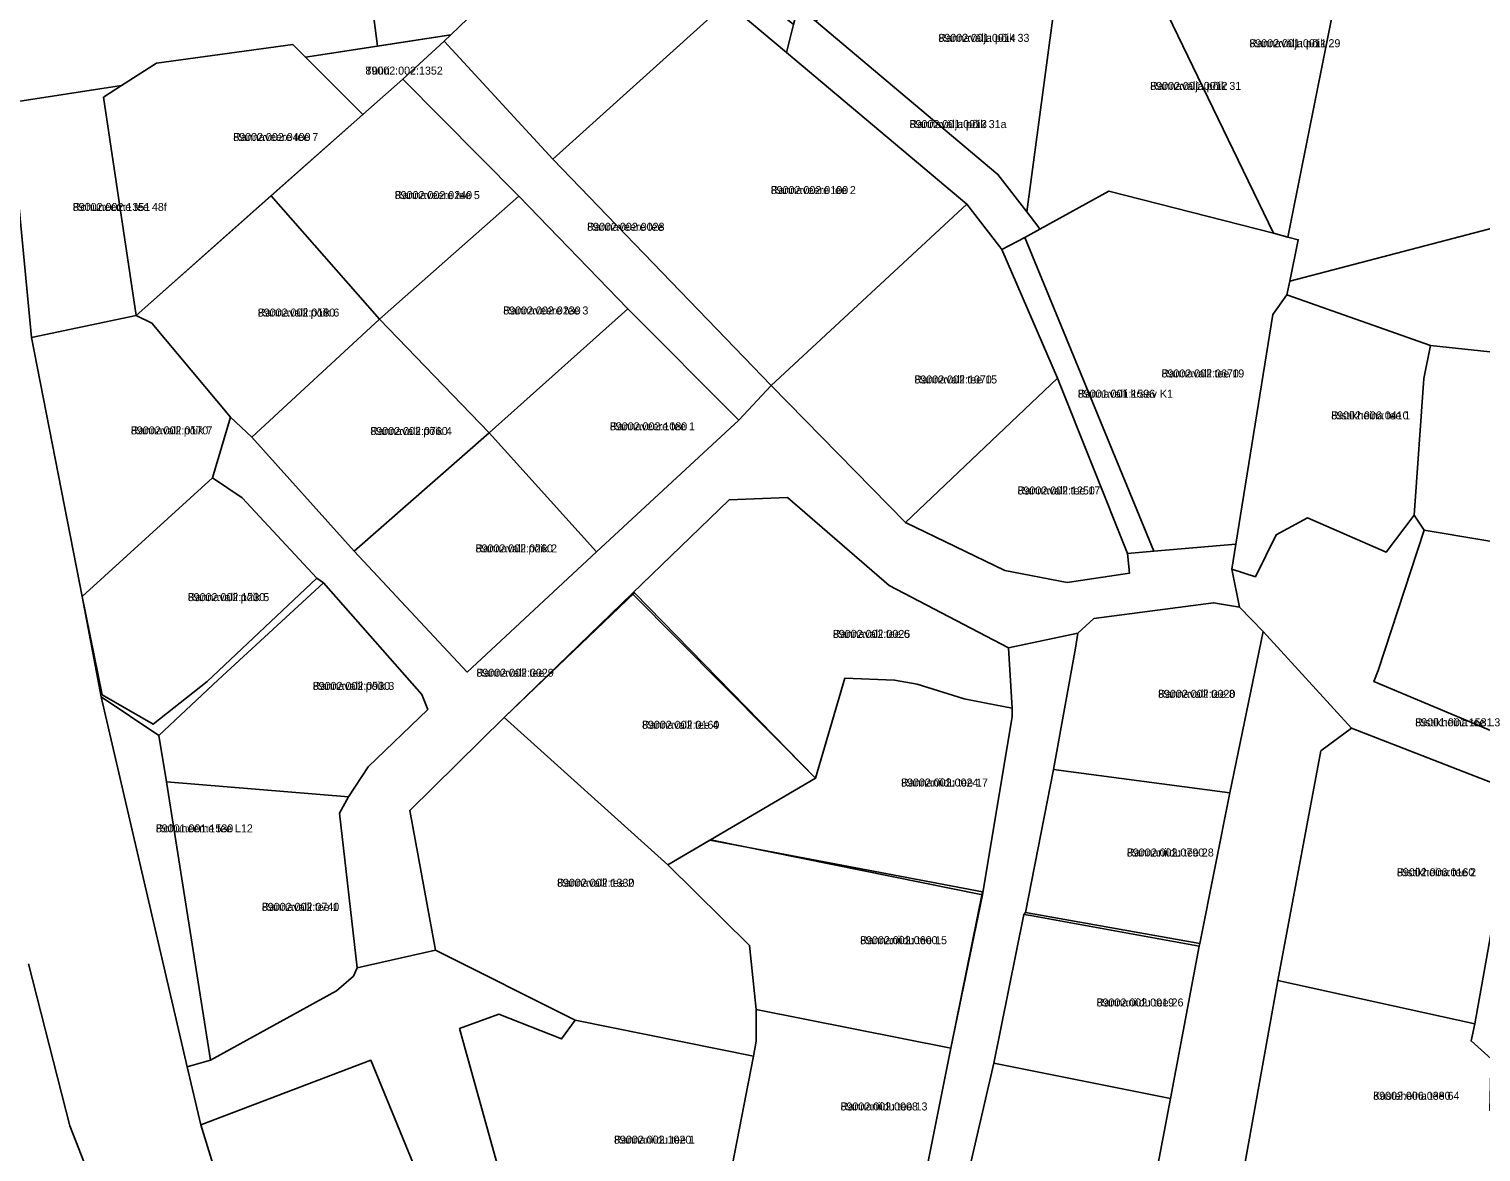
# Model space of a CAD drawing. Extents: x 526849 to 562296, y 6591741 to 6618546.
# Drawn here: x 545079.1 to 545351.2, y 6599278.2 to 6599488.6 of the extents above; entities that cross this region are included whole.
import ezdxf

# ---------------------------------------------------------------- set-up
doc = ezdxf.new("R2010")
doc.units = 0
for name, color, linetype in [('L_AADRESS', 7, 'Continuous'), ('PIIR', 7, 'Continuous'), ('TUNNUS', 7, 'Continuous')]:
    doc.layers.add(name, color=color, linetype=linetype)

msp = doc.modelspace()

# ---------------------------------------------------------------- linework, layer by layer
at = {"layer": 'PIIR'}
for points in [[(545405.74, 6599650.28), (545389.3, 6599566.67), (545376.43, 6599503.88), (545367.66, 6599457.32), (545373.86, 6599456.64), (545315.4, 6599441.37), (545316.99, 6599449.14), (545315.05, 6599449.64), (545318.74, 6599468.03), (545327.84, 6599513.78), (545329.66, 6599522.77), (545334.02, 6599544.69), (545338.46, 6599566.76), (545341.92, 6599584.34), (545343.79, 6599593.87), (545346.85, 6599609.12), (545353.41, 6599641.84), (545356.94, 6599659.68)], [(545219.07, 6599657.56), (545210.56, 6599616.75), (545209.57, 6599612.32), (545202.52, 6599580.46), (545198.72, 6599563.34), (545191.91, 6599531.05), (545190.99, 6599524.12), (545191.51, 6599518.55), (545193.48, 6599514.29), (545197.05, 6599510.92), (545213.13, 6599497.04), (545222.37, 6599489.43), (545221.07, 6599484.2), (545209.87, 6599493.59), (545188.88, 6599516.39), (545185.2, 6599519.83), (545185.44, 6599525.77), (545192.45, 6599555.16), (545199.86, 6599586.6), (545206.47, 6599614.63), (545212.72, 6599645.15)], [(545161.38, 6599490.6), (545158.2, 6599487.55), (545144.45, 6599485.43), (545139.36, 6599524.52)], [(545075.42, 6599474.76), (545079.57, 6599430.82), (545089.09, 6599382.3), (545092.64, 6599363.49), (545108.78, 6599294.19), (545111.31, 6599283.27), (545121.94, 6599248.78)], [(545287.34, 6599258.34), (545293.06, 6599288.24), (545298.44, 6599316.78), (545298.54, 6599317.27), (545304.14, 6599345.48), (545310.42, 6599375.7), (545326.93, 6599357.61), (545321.18, 6599353.36), (545313.14, 6599310.34), (545306.14, 6599271.41)], [(545245.73, 6599267.08), (545251.84, 6599297.64), (545257.81, 6599326.38), (545263.37, 6599359.83), (545263.37, 6599361.37), (545262.7, 6599372.66), (545275.68, 6599375.4), (545275.22, 6599372.58), (545271.14, 6599349.86), (545265.89, 6599323.09), (545265.55, 6599322.7), (545259.91, 6599294.83), (545253.11, 6599265.42)], [(545156.14, 6599263.74), (545143.19, 6599295.41), (545111.31, 6599283.27), (545108.78, 6599294.19), (545113.11, 6599295.38), (545136.77, 6599308.43), (545139.9, 6599311.17), (545140.61, 6599312.71), (545155.32, 6599315.99), (545181.44, 6599302.92), (545178.92, 6599299.39), (545167.16, 6599304.04), (545159.81, 6599301.33), (545170.81, 6599261.82)], [(545093.24, 6599266.51), (545086.79, 6599283.13), (545079, 6599313.45)], [(545079, 6599313.45), (545086.79, 6599283.13), (545093.24, 6599266.51)]]:
    msp.add_lwpolyline(points, dxfattribs=at)
for points in [[(545139.36, 6599524.52), (545144.45, 6599485.43), (545130.94, 6599483.34), (545128.54, 6599485.74), (545103.01, 6599482.21), (545096.48, 6599478.02), (545075.42, 6599474.76), (545071.2, 6599518.36)], [(545209.87, 6599493.59), (545177.29, 6599464.21), (545156.9, 6599486.32), (545158.2, 6599487.55), (545161.38, 6599490.6), (545188.88, 6599516.39)], [(545294.41, 6599508.59), (545327.84, 6599513.78), (545318.74, 6599468.03), (545315.05, 6599449.64), (545312.35, 6599450.34), (545287.77, 6599501.13), (545291.51, 6599504.25)], [(545228.74, 6599498.45), (545268.16, 6599504.54), (545272.37, 6599501), (545266.11, 6599454.34), (545260.71, 6599461.36), (545226.69, 6599489.93)], [(545272.37, 6599501), (545277.72, 6599499.07), (545283.35, 6599499.29), (545287.77, 6599501.13), (545312.35, 6599450.34), (545281.51, 6599458.26), (545268.57, 6599451.12), (545268.15, 6599451.67), (545266.11, 6599454.34)], [(545254.9, 6599455.8), (545218.23, 6599421.79), (545177.29, 6599464.21), (545209.87, 6599493.59), (545221.07, 6599484.2)], [(545223.27, 6599492.8), (545226.69, 6599489.93), (545260.71, 6599461.36), (545266.11, 6599454.34), (545268.15, 6599451.67), (545268.57, 6599451.12), (545265.71, 6599449.54), (545261.41, 6599447.3), (545261.06, 6599447.78), (545254.9, 6599455.8), (545221.07, 6599484.2), (545222.37, 6599489.43), (545222.91, 6599491.31)], [(545158.2, 6599487.55), (545156.9, 6599486.32), (545149.2, 6599479.24), (545141.7, 6599472.58), (545130.94, 6599483.34)], [(545099.22, 6599434.93), (545093.06, 6599475.82), (545096.48, 6599478.02), (545103.01, 6599482.21), (545128.54, 6599485.74), (545130.94, 6599483.34), (545141.7, 6599472.58), (545124.46, 6599457.34)], [(545218.23, 6599421.79), (545212.13, 6599415.32), (545191.37, 6599436.16), (545170.9, 6599457.29), (545149.2, 6599479.24), (545156.9, 6599486.32), (545177.29, 6599464.21)], [(545141.7, 6599472.58), (545149.2, 6599479.24), (545170.9, 6599457.29), (545144.78, 6599434.27), (545124.5, 6599457.33)], [(545096.48, 6599478.02), (545093.06, 6599475.82), (545099.22, 6599434.93), (545079.57, 6599430.82), (545075.42, 6599474.76)], [(545314.83, 6599438.78), (545315.4, 6599441.37), (545373.86, 6599456.64), (545446.15, 6599449.22), (545466.37, 6599454.08), (545508.73, 6599465.77), (545513.69, 6599449.89), (545413.33, 6599420.67), (545376.31, 6599425.64), (545341.78, 6599429.33)], [(545116.85, 6599415.88), (545102.15, 6599433.53), (545099.22, 6599434.93), (545124.5, 6599457.33), (545144.78, 6599434.27), (545120.88, 6599412.15)], [(545144.78, 6599434.27), (545170.9, 6599457.29), (545191.37, 6599436.16), (545165.36, 6599412.97)], [(545281.51, 6599458.26), (545312.35, 6599450.34), (545315.05, 6599449.64), (545316.99, 6599449.14), (545315.4, 6599441.37), (545314.83, 6599438.78), (545312.21, 6599435.13), (545305.28, 6599392.09), (545289.94, 6599390.81), (545265.71, 6599449.54), (545268.57, 6599451.12)], [(545271.86, 6599423.21), (545243.35, 6599396.13), (545218.23, 6599421.79), (545254.9, 6599455.8), (545261.06, 6599447.78), (545261.41, 6599447.3)], [(545265.71, 6599449.54), (545289.94, 6599390.81), (545285, 6599390.36), (545271.86, 6599423.21), (545261.41, 6599447.3)], [(545312.86, 6599393.85), (545308.96, 6599385.98), (545304.52, 6599387.4), (545305.28, 6599392.09), (545312.21, 6599435.13), (545314.83, 6599438.78), (545341.78, 6599429.33), (545340.51, 6599423.13), (545338.71, 6599397.5), (545333.45, 6599390.58), (545318.7, 6599397.03)], [(545165.36, 6599412.97), (545191.37, 6599436.16), (545212.13, 6599415.32), (545185.48, 6599390.68)], [(545079.57, 6599430.82), (545099.22, 6599434.93), (545102.15, 6599433.53), (545116.85, 6599415.88), (545113.48, 6599404.49), (545089.09, 6599382.3)], [(545120.88, 6599412.15), (545144.78, 6599434.27), (545165.36, 6599412.97), (545140.03, 6599390.8)], [(545338.71, 6599397.5), (545340.51, 6599423.13), (545341.78, 6599429.33), (545376.31, 6599425.64), (545375.21, 6599419.53), (545372.61, 6599389.33), (545340.58, 6599394.69)], [(545261.97, 6599387.18), (545243.35, 6599396.13), (545271.86, 6599423.21), (545285, 6599390.36), (545285.38, 6599386.68), (545273.65, 6599384.92)], [(545155.32, 6599315.99), (545140.61, 6599312.71), (545137.32, 6599341.71), (545139, 6599344.73), (545142.65, 6599350.34), (545153.83, 6599361.09), (545152.76, 6599363.95), (545134.3, 6599384.82), (545133.04, 6599385.73), (545119.04, 6599400.76), (545113.48, 6599404.49), (545116.85, 6599415.88), (545120.88, 6599412.15), (545140.03, 6599390.8), (545161.24, 6599368.13), (545185.48, 6599390.68), (545212.13, 6599415.32), (545218.23, 6599421.79), (545243.35, 6599396.13), (545261.97, 6599387.18), (545273.65, 6599384.92), (545285.38, 6599386.68), (545285, 6599390.36), (545289.94, 6599390.81), (545305.28, 6599392.09), (545304.52, 6599387.4), (545305.97, 6599380.3), (545301.12, 6599381.13), (545278.64, 6599378.16), (545275.68, 6599375.4), (545262.7, 6599372.66), (545240.34, 6599384.37), (545221.25, 6599400.84), (545210.31, 6599400.37), (545192.17, 6599382.84), (545168.18, 6599359.61), (545150.48, 6599342.22)], [(545140.03, 6599390.8), (545165.36, 6599412.97), (545185.48, 6599390.68), (545161.24, 6599368.13)], [(545092.82, 6599363.87), (545089.09, 6599382.3), (545113.48, 6599404.49), (545119.04, 6599400.76), (545133.04, 6599385.73), (545112.53, 6599366.38), (545102.37, 6599358.36)], [(545192.17, 6599382.84), (545210.31, 6599400.37), (545221.25, 6599400.84), (545240.34, 6599384.37), (545262.7, 6599372.66), (545263.37, 6599361.37), (545258.48, 6599362.31), (545254.37, 6599363.12), (545245.56, 6599365.87), (545241.34, 6599366.62), (545232.03, 6599366.98), (545226.52, 6599348.22)], [(545308.96, 6599385.98), (545312.86, 6599393.85), (545318.7, 6599397.03), (545333.45, 6599390.58), (545338.71, 6599397.5), (545340.58, 6599394.69), (545331.93, 6599368.39), (545331.17, 6599366.34), (545368.2, 6599350.83), (545403.96, 6599334.94), (545411.28, 6599331.68), (545418.49, 6599329.94), (545420.77, 6599318.43), (545383.36, 6599334.01), (545357.8, 6599345.64), (545326.93, 6599357.61), (545310.42, 6599375.7), (545305.97, 6599380.3), (545304.52, 6599387.4)], [(545331.93, 6599368.39), (545340.58, 6599394.69), (545372.61, 6599389.33), (545369.16, 6599355.14), (545368.2, 6599350.83), (545331.17, 6599366.34)], [(545134.3, 6599384.82), (545152.76, 6599363.95), (545153.83, 6599361.09), (545142.65, 6599350.34), (545139, 6599344.73), (545104.88, 6599347.56), (545103.44, 6599356.26), (545114.56, 6599366.66)], [(545226.52, 6599348.22), (545206.85, 6599336.69), (545198.84, 6599332.02), (545168.18, 6599359.61), (545192.6, 6599382.98)], [(545271.14, 6599349.86), (545275.22, 6599372.58), (545275.68, 6599375.4), (545278.64, 6599378.16), (545301.12, 6599381.13), (545305.97, 6599380.3), (545310.42, 6599375.7), (545304.14, 6599345.48)], [(545206.85, 6599336.69), (545226.52, 6599348.22), (545232.03, 6599366.98), (545241.34, 6599366.62), (545245.56, 6599365.87), (545254.37, 6599363.12), (545258.48, 6599362.31), (545263.37, 6599361.37), (545263.37, 6599359.83), (545257.81, 6599326.38)], [(545108.78, 6599294.19), (545092.64, 6599363.49), (545103.44, 6599356.26), (545104.88, 6599347.56), (545113.11, 6599295.38)], [(545155.32, 6599315.99), (545150.48, 6599342.22), (545168.18, 6599359.61), (545198.84, 6599332.02), (545214.17, 6599316.92), (545215.4, 6599304.9), (545215.39, 6599298.94), (545214.86, 6599296.19), (545181.44, 6599302.92)], [(545321.18, 6599353.36), (545326.93, 6599357.61), (545357.8, 6599345.64), (545350.07, 6599302.23), (545313.14, 6599310.34)], [(545271.14, 6599349.86), (545304.14, 6599345.48), (545298.54, 6599317.27), (545265.89, 6599323.09)], [(545104.88, 6599347.56), (545139, 6599344.73), (545137.32, 6599341.71), (545140.61, 6599312.71), (545139.9, 6599311.17), (545136.77, 6599308.43), (545113.11, 6599295.38)], [(545350.07, 6599302.23), (545357.8, 6599345.64), (545383.36, 6599334.01), (545382.2, 6599326.89), (545375.26, 6599292.03), (545362.46, 6599284.03), (545356.46, 6599285.33), (545352.86, 6599286.03), (545353.16, 6599295.63), (545349.36, 6599299.03)], [(545214.17, 6599316.92), (545198.84, 6599332.02), (545206.71, 6599336.64), (545257.78, 6599326.92), (545251.84, 6599297.64), (545215.4, 6599304.9)], [(545265.55, 6599322.7), (545266.81, 6599322.54), (545298.44, 6599316.78), (545293.06, 6599288.24), (545259.91, 6599294.83)], [(545306.14, 6599271.41), (545313.14, 6599310.34), (545350.07, 6599302.23), (545349.36, 6599299.03), (545353.16, 6599295.63), (545352.86, 6599286.03), (545356.46, 6599285.33), (545352.36, 6599267.94), (545343.08, 6599269.42), (545341.66, 6599265.63)], [(545159.81, 6599301.33), (545167.16, 6599304.04), (545178.92, 6599299.39), (545181.44, 6599302.92), (545214.86, 6599296.19), (545210.87, 6599275.62), (545206.87, 6599255.49), (545170.81, 6599261.82)], [(545214.86, 6599296.19), (545215.39, 6599298.94), (545215.4, 6599304.9), (545251.84, 6599297.64), (545245.73, 6599267.08), (545210.87, 6599275.62)], [(545121.94, 6599248.78), (545111.31, 6599283.27), (545143.19, 6599295.41), (545156.14, 6599263.74), (545155.46, 6599260.08)], [(545253.11, 6599265.42), (545259.91, 6599294.83), (545293.06, 6599288.24), (545287.34, 6599258.34)]]:
    msp.add_lwpolyline(points, close=True, dxfattribs=at)

# ---------------------------------------------------------------- texts
at = {"layer": 'L_AADRESS'}
for s, p in [('Rannavälja põik 33', (545249.53, 6599486.21)), ('Rannavälja põik 29', (545307.81, 6599485.2)), ('Tüüri', (545142.16, 6599480.07)), ('Rannavälja põik 31', (545289.23, 6599477.2)), ('Rannavälja põik 31a', (545244.14, 6599470.05)), ('Rannaveere tee 7', (545117.38, 6599467.63)), ('Rannaveere tee 5', (545147.65, 6599456.75)), ('Rannaveere tee 2', (545218.12, 6599457.69)), ('Rohuneeme tee 48f', (545087.32, 6599454.52)), ('Rannaveere tee', (545183.71, 6599450.81)), ('Rannavalli põik 6', (545121.99, 6599434.74)), ('Rannaveere tee 3', (545167.99, 6599435.13)), ('Rannavalli tee 19', (545291.35, 6599423.33)), ('Rannavalli tee 15', (545245.04, 6599422.2)), ('Rannavalli kraav K1', (545275.67, 6599419.53)), ('Ristikheina tee 1', (545323.15, 6599415.47)), ('Rannavalli põik 7', (545098.21, 6599412.66)), ('Rannavalli põik 4', (545143.08, 6599412.54)), ('Rannaveere tee 1', (545187.97, 6599413.42)), ('Rannavalli tee 17', (545264.37, 6599401.4)), ('Rannavalli põik 2', (545162.8, 6599390.55)), ('Rannavalli põik 5', (545108.87, 6599381.42)), ('Rannavalli tee 6', (545229.77, 6599374.53)), ('Rannavalli tee', (545162.96, 6599367.25)), ('Rannavalli põik 3', (545132.29, 6599364.78)), ('Rannavalli tee 8', (545290.7, 6599363.3)), ('Ristikheina tee L3', (545338.89, 6599357.96)), ('Rannavalli tee 4', (545193.99, 6599357.5)), ('Rannaniidu tee 17', (545242.54, 6599346.68)), ('Rohuneeme tee L12', (545102.88, 6599338.09)), ('Rannaniidu tee 28', (545284.86, 6599333.57)), ('Rannavalli tee 2', (545178.07, 6599327.9)), ('Ristikheina tee 2', (545335.47, 6599329.87)), ('Rannavalli tee 1', (545122.75, 6599323.39)), ('Rannaniidu tee 15', (545234.87, 6599317.14)), ('Rannaniidu tee 26', (545279.19, 6599305.47)), ('Kasteheina tee 64', (545331.02, 6599287.99)), ('Rannaniidu tee 13', (545231.2, 6599285.99)), ('Rannaniidu tee 1', (545188.74, 6599279.76))]:
    msp.add_text(s, height=1.5, dxfattribs=at).set_placement(p)
at = {"layer": 'TUNNUS'}
for s, p in [('89002:001:0014', (545249.53, 6599486.21)), ('89002:001:0011', (545307.81, 6599485.2)), ('89002:002:1352', (545142.16, 6599480.07)), ('89002:001:0012', (545289.23, 6599477.2)), ('89002:001:0013', (545244.14, 6599470.05)), ('89002:002:0400', (545117.38, 6599467.63)), ('89002:002:0240', (545147.65, 6599456.75)), ('89002:002:0100', (545218.12, 6599457.69)), ('89002:002:1351', (545087.32, 6599454.52)), ('89002:002:0028', (545183.71, 6599450.81)), ('89002:002:0180', (545121.99, 6599434.74)), ('89002:002:0230', (545167.99, 6599435.13)), ('89002:002:0670', (545291.35, 6599423.33)), ('89002:002:1070', (545245.04, 6599422.2)), ('89001:001:1596', (545275.67, 6599419.53)), ('89002:006:0410', (545323.15, 6599415.47)), ('89002:002:0170', (545098.21, 6599412.66)), ('89002:002:0760', (545143.08, 6599412.54)), ('89002:002:1080', (545187.97, 6599413.42)), ('89002:002:1250', (545264.37, 6599401.4)), ('89002:002:0260', (545162.8, 6599390.55)), ('89002:002:1230', (545108.87, 6599381.42)), ('89002:002:0025', (545229.77, 6599374.53)), ('89002:002:0029', (545162.96, 6599367.25)), ('89002:002:0930', (545132.29, 6599364.78)), ('89002:002:0020', (545290.7, 6599363.3)), ('89001:001:1581', (545338.89, 6599357.96)), ('89002:002:0160', (545193.99, 6599357.5)), ('89002:002:0024', (545242.54, 6599346.68)), ('89001:001:1530', (545102.88, 6599338.09)), ('89002:002:0790', (545284.86, 6599333.57)), ('89002:002:1330', (545178.07, 6599327.9)), ('89002:006:0160', (545335.47, 6599329.87)), ('89002:002:0740', (545122.75, 6599323.39)), ('89002:002:0600', (545234.87, 6599317.14)), ('89002:002:0019', (545279.19, 6599305.47)), ('89002:006:0380', (545331.02, 6599287.99)), ('89002:002:0008', (545231.2, 6599285.99)), ('89002:002:1020', (545188.74, 6599279.76))]:
    msp.add_text(s, height=1.5, dxfattribs=at).set_placement(p)

doc.saveas('drawing.dxf')
